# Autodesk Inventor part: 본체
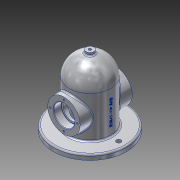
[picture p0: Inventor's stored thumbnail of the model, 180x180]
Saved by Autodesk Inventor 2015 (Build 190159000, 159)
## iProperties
Created: 2019-11
Part Number: 본체
Material: 알루미늄 6061
Document SubType Name: Modeling
Designer: LINEART-SSD.D4.16.07
Density: 2.7 g/cm^3
Appearance: 알루미늄 - 평지
Mass: 1105.87 g
Surface Area: 883.886 cm^2
Volume: 409.581 cm^3
Author: LINEART-SSD.D4.16.07
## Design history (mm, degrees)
sketch "스케치1"
  geometry: C1 r 70 at (0, 0); 1 further point
  constraints: 1 centre point, 1 coincident
  dimensions: "d0" = 140 diameter of C1
extrude "돌출1" new body sketch "스케치1" distance "d1" = 10; taper "d2" = 0 deg
sketch "스케치2"
  geometry: C1 r 70 at (0, 0) reference; C2 r 40 at (0, 0); 1 further point
  constraints: 1 centre point, 1 coincident
  dimensions: "d3" = 80 diameter of C2
extrude "돌출2" join sketch "스케치2" distance "d4" = 80; taper "d5" = 0 deg
sketch "스케치3"
  geometry: L1 (40, 90)-(-40, 90) reference; L2 (-40, 10)-(40, 10) reference; L3 (0, 90)-(0, 130); L4 (0, 90)-(-40, 90); L5 (40, 90)-(-40, 90) reference; A1 r 40 centre (0, 90) between (0, 130) and (-40, 90); 1 further point
  constraints: 6 end point, 2 point on circle, 1 centre point, 1 collinear, 1 midpoint
  dimensions: "d7" = 90 deg angle of L3 L1
revolve "회전1" sketch "스케치3" stored, may be unused: angle "d8" = 90 deg
node "작업 평면1"
sketch "스케치4"
  geometry: L1 (0, 0)-(0, 50); C1 r 31 at (0, 50)
  constraints: 2 end point, 1 centre point, 1 coincident, 1 vertical
  dimensions: "d10" = 50 distance of L1.start L1.end; "d11" = 62 diameter of C1
extrude "돌출3" join sketch "스케치4" stored distance "d12" = 80; taper "d13" = 0 deg
node "작업 평면2"
sketch "스케치5"
  geometry: L1 (0, 0)-(0, 50); C1 r 31 at (0, 50)
  constraints: 2 end point, 1 centre point, 1 coincident, 1 vertical
  dimensions: "d15" = 50 distance of L1.start L1.end; "d16" = 62 diameter of C1
extrude "돌출4" join sketch "스케치5" stored distance "d17" = 80; taper "d18" = 0 deg
sketch "스케치6"
  geometry: C1 r 31 at (0, 0) reference; A1 r 26 centre (0, 0) between (0, -26) and (26, 0); 3 further points
  constraints: 4 point on circle, 1 centre point, 1 coincident
  dimensions: "d19" = 52 diameter of A1; "d20" = 36.76955 distance of point (-26, 0) A1.start; "d21" = 36.76955 distance of point (-26, 0) point (0, 26); "d22" = 36.76955 distance of point (0, 26) A1.end; "d23" = 26 horizontal distance of A1.end A1.start
hole "구멍1" sketch "스케치6" at (0, -26), (26, 0), (0, 26), (-26, 0) diameter "d24" = 3.459; stored, may be unused: countersink angle "d28" = 90 deg, drill point angle "d30" = 118 deg; dims "d25" = 8, "d26" = 4, "d27" = 2, "d29" = 10
sketch "스케치7"
  geometry: C1 r 1.73 at (0, 26) reference; C2 r 1.73 at (0, -26) reference; C3 r 1.73 at (26, 0) reference; C4 r 1.73 at (-26, 0) reference; C5 r 31 at (0, 0) reference; C6 r 20 at (0, 0); 1 further point
  constraints: 1 centre point, 1 coincident
  dimensions: "d31" = 40 diameter of C6
extrude "돌출5" cut sketch "스케치7" distance "d32" = 15; taper "d33" = 0 deg
sketch "스케치8"
  geometry: C1 r 31 at (0, 0) reference; C2 r 16.5 at (0, 0); 1 further point
  constraints: 1 centre point, 1 coincident
  dimensions: "d34" = 33 diameter of C2
extrude "돌출6" cut sketch "스케치8" stored distance "d35" = 15; taper "d36" = 0 deg
sketch "스케치9"
  geometry: C1 r 16.5 at (0, 0) reference; C2 r 31 at (0, 0) reference; C3 r 1.73 at (0, 26) reference; C4 r 1.73 at (0, -26) reference; A1 r 26 centre (0, 0) between (-26, 0) and (26, 0); 3 further points
  constraints: 3 coincident, 2 point on circle, 1 centre point
  dimensions: "d37" = 52 diameter of A1; "d38" = 36.76955 distance of A1.end point (0, 26); "d39" = 36.76955 distance of A1.start point (0, -26)
hole "구멍2" sketch "스케치9" at (0, 26), (-26, 0), (0, -26), (26, 0) diameter "d40" = 3.459; stored, may be unused: countersink angle "d44" = 90 deg, drill point angle "d46" = 118 deg; dims "d41" = 8, "d42" = 4, "d43" = 2, "d45" = 10
sketch "스케치10"
  geometry: C1 r 20 at (0, 0) reference; C2 r 1.73 at (0, -26) reference; C3 r 1.73 at (0, 26) reference; C4 r 1.73 at (26, 0) reference; C5 r 1.73 at (-26, 0) reference; C6 r 31 at (0, 0) reference; C7 r 20 at (0, 0); 1 further point
  constraints: 1 centre point, 1 coincident
  dimensions: "d47" = 40 diameter of C7
extrude "돌출7" cut sketch "스케치10" distance "d48" = 15; taper "d49" = 0 deg
node "작업 평면3"
sketch "스케치11"
  geometry: C1 r 7.5 at (0, 0); 1 further point
  constraints: 1 centre point, 1 coincident
  dimensions: "d51" = 15 diameter of C1
extrude "돌출8" join sketch "스케치11" stored distance "d52" = 15; taper "d53" = 0 deg
sketch "스케치12"
  geometry: C1 r 7.5 at (0, 0) reference; 2 further points
  constraints: 1 coincident
hole "구멍3" sketch "스케치12" at (0, 0) diameter "d54" = 5.188; stored, may be unused: countersink angle "d58" = 90 deg, drill point angle "d60" = 118 deg; dims "d55" = 12, "d56" = 4, "d57" = 2, "d59" = 16
sketch "스케치13"
  geometry: C1 r 2.594 at (0, 0) reference; C2 r 70 at (0, 0) reference; C3 r 30 at (0, 0); 1 further point
  constraints: 1 centre point, 1 coincident
  dimensions: "d61" = 60 diameter of C3
extrude "돌출9" cut sketch "스케치13" distance "d62" = 90; taper "d63" = 0 deg
sketch "스케치14"
  geometry: L1 (-7.5, 129.291)-(7.5, 129.291) reference; L2 (40, 90)-(-40, 90) reference; L3 (0, 90)-(0, 120); L4 (0, 90)-(30, 90); A1 r 30 centre (0, 90) between (30, 90) and (0, 120); 1 further point
  constraints: 4 end point, 2 point on circle, 1 centre point, 1 collinear, 1 midpoint, 1 point on line
  dimensions: "d66" = 90 deg angle of L2 L3; "d67" = 30 radius of A1
revolve "회전2" sketch "스케치14" stored, may be unused: angle "d68" = 90 deg
sketch "스케치15"
  geometry: L1 (0, 0)-(-55, 0); L2 (0, 0)-(55, 0); C1 r 40 at (0, 0) reference; C2 r 70 at (0, 0) reference; C3 r 4.5 at (-55, 0); C4 r 4.5 at (55, 0); C5 r 2.594 at (0, 0) reference; A1 r 55 centre (0, 0) between (-55, 0) and (55, 0); 1 further point
  constraints: 4 end point, 3 centre point, 2 horizontal, 2 point on circle, 1 coincident
  dimensions: "d69" = 110 diameter of A1; "d70" = 9 diameter of C3; "d71" = 9 diameter of C4
extrude "돌출10" cut sketch "스케치15" stored distance "d72" = 90; taper "d73" = 0 deg
fillet "모깎기1" dims "d74" = 3
fillet "모깎기2" dims "d75" = 0.3
chamfer "모따기1" distance "d76" = 1; stored, may be unused: second distance "d77" = 2, angle "d78" = 45 deg
node "작업 평면4"
sketch "스케치17"
  geometry: L1 (0, 0)-(0, 50); 1 further point
  constraints: 2 end point, 1 coincident, 1 vertical, 1 other
  dimensions: "d83" = 50 distance of L1.start L1.end
feature "엠보싱2" sketch "스케치17" dims "d84" = 0.5, "d85" = 0
node "솔리드1"
node "투영된 루프1"
node "투영된 루프2"
node "투영된 루프3"
node "투영된 루프4"
node "투영된 루프5"
node "투영된 루프6"
node "투영된 루프7"
node "투영된 루프8"
node "투영된 루프9"
node "투영된 루프10"
node "투영된 루프11"
other parameters: "d50" = 135
